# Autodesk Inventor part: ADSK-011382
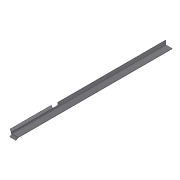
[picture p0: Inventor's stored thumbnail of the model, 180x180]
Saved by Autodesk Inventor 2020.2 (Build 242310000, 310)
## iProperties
Created: 1999-12
Part Number: ADSK-011382
Material: 1.0312 DC05
Document SubType Name: Tôlerie
Designer: sspink
Density: 1 g/cm^3
Sheet Metal Rule: Stahlblech 1.0312 - DC05 -   3.0 mm
Appearance: Metal-Steel(Polish)
Mass: 468.169 g
Surface Area: 3221.87 cm^2
Volume: 468.169 cm^3
Sheet Metal Width: 102,286 mm
Sheet Metal Length: 1548,047 mm
Sheet Metal Area: 158343,243 mm^2
Flat Pattern Width: 10.2286 cm
Flat Pattern Length: 154.805 cm
Flat Pattern Area: 1583.43 cm^2
Control State: 0
Master: False
Checked Out: False
Shininess: 57.0
Length Units: 11269
Angle Units: 11279
Time Units: 11290
Mass Units: 11283
Length Display Precision: 3
Angle Display Precision: 2
Compacted: True
CUTLENGTH: 3.81 X 61.03 (233 SI)
MATERIAL DESC: SHEET,S/S, 11 GA
MATERIAL_NUMBER: A084638
G_L: 102,3x1548 mm
Thickness: 3,000 mm
Dimensions: 53,1x1545,7x78,6 mm
Mass: 0,468 kg
Semi finished: Stahlblech 1.0312 - DC05 -   3.0 mm
VLT_Material: 1.0312 DC05
Density: 8.03
Volumn: 482.19162532113285
Area: 3142.4654297786715
PropertySet Name: Model Information
Author: sspink
Revision Number: -
Title: ADSK-011382
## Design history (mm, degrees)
node "Solide1"
  node "Konturlasche1"
  node "Lasche1"
  node "Lasche2"
sketch "Sketch1"
  geometry: L1 (0, 0)-(0, 38); L2 (0, 0)-(63.5, 0); 1 further point
  constraints: 4 end point, 1 coincident, 1 horizontal, 1 perpendicular
  dimensions: "d56" = 63.5 distance of L1.start L2.end; "d57" = 38 distance of L1.start L1.end
sketch "Skizze13"
  geometry: L1 (0, 460)-(0, 54); L2 (0, 54)-(25, 54); L3 (25, 54)-(25, 460); L4 (25, 460)-(0, 460)
  constraints: 8 end point
feature "Grobblech3" dims "d55" = 3 (= Thickness), "d82" = 3 (= BendReliefWidth), "d83" = 1.5 (= BendReliefDepth), "d84" = 6 (= MinimumRemnant), "d85" = 3 (= TransitionRadius), "d86" = 406, "d87" = 0, "d88" = 25, "d89" = 30 deg, "d90" = 3 (= BendRadius), "d91" = 12 (= CornerReliefSize), "d92" = 3 (= TailleJeu), "d93" = 3 (= TailleRayonJacobi), "SeamGap" = 0.00508
feature "Biegung6" dims "d55" = 3 (= Thickness), "d82" = 3 (= BendReliefWidth), "d83" = 1.5 (= BendReliefDepth), "d84" = 6 (= MinimumRemnant), "d85" = 3 (= TransitionRadius), "d88" = 25, "d89" = 30 deg, "d90" = 3 (= BendRadius), "SeamGap" = 0.00508
feature "Ecke3" dims "d88" = 25, "d89" = 30 deg, "d91" = 12 (= CornerReliefSize), "d92" = 3 (= TailleJeu), "d93" = 3 (= TailleRayonJacobi)
feature "Grobblech1" dims "d55" = 3 (= Thickness), "d58" = 3 (= BendReliefWidth), "d59" = 1.5 (= BendReliefDepth), "d60" = 6 (= MinimumRemnant), "d61" = 3 (= TransitionRadius), "d62" = 1524, "d63" = 3 (= BendRadius), "d64" = 3, "d65" = 12 (= CornerReliefSize), "d66" = 3 (= TailleJeu), "d67" = 3 (= TailleRayonJacobi), "SeamGap" = 0.00508
feature "Biegung4" dims "d55" = 3 (= Thickness), "d58" = 3 (= BendReliefWidth), "d59" = 1.5 (= BendReliefDepth), "d60" = 6 (= MinimumRemnant), "d61" = 3 (= TransitionRadius), "d63" = 3 (= BendRadius), "d64" = 3, "SeamGap" = 0.00508
feature "Ecke1" dims "d64" = 3, "d65" = 12 (= CornerReliefSize), "d66" = 3 (= TailleJeu), "d67" = 3 (= TailleRayonJacobi)
sketch "Skizze11"
  geometry: L1 through (-30.25, 0) direction (1, -1.04e-17); L2 through (0, 12.5) direction (-8.53e-18, 1); L3 (0, 25)-(-60.5, 25); L4 (-60.5, 25)-(-60.5, 0)
  constraints: 6 end point, 1 horizontal, 1 perpendicular, 1 vertical
feature "Grobblech2" dims "d55" = 3 (= Thickness), "d68" = 3 (= BendReliefWidth), "d69" = 1.5 (= BendReliefDepth), "d70" = 6 (= MinimumRemnant), "d71" = 3 (= TransitionRadius), "d72" = 25, "d73" = 30 deg, "d74" = 3 (= BendRadius), "d75" = 12 (= CornerReliefSize), "d76" = 3 (= TailleJeu), "d77" = 3 (= TailleRayonJacobi), "SeamGap" = 0.00508
feature "Biegung5" dims "d55" = 3 (= Thickness), "d68" = 3 (= BendReliefWidth), "d69" = 1.5 (= BendReliefDepth), "d70" = 6 (= MinimumRemnant), "d71" = 3 (= TransitionRadius), "d72" = 25, "d73" = 30 deg, "d74" = 3 (= BendRadius), "SeamGap" = 0.00508
feature "Ecke2" dims "d72" = 25, "d73" = 30 deg, "d75" = 12 (= CornerReliefSize), "d76" = 3 (= TailleJeu), "d77" = 3 (= TailleRayonJacobi)
sketch "Skizze12"
  geometry: L1 (0, 0)-(1524, 0) reference; L2 (1524, 0)-(1524, -35) reference; L3 (1064, 0)-(1064, -25); L4 (1064, -25)-(1524, -25); 1 further point
  constraints: 4 end point, 2 point on line, 1 horizontal, 1 vertical
  dimensions: "d78" = 460 distance of L3.end L4.end; "d79" = 25 distance of L3.start L3.end
feature "Ausklinkung1" dims "d80" = 3 (= Thickness), "d81" = 0
node "Corps solides"
node "Corps surfaciques"
feature "Definition1"
other parameters: "Thickness" = 3 (derived), "BendRadius" = 3 (= Thickness), "BendReliefWidth" = 3 (= Thickness), "BendReliefDepth" = 1.5 (= 0.5 x Thickness), "CornerReliefSize" = 12 (= 4 x Thickness), "MinimumRemnant" = 6 (= 2 x Thickness), "TransitionRadius" = 3 (= BendRadius), "TailleRayonJacobi" = 3 (= BendRadius), "TailleJeu" = 3 (= Thickness), "Thickness_Kopieren" = 3.175 [user parameter], "Thickness_Kopieren" = 3.175, "BendRadius" = 3, "BendReliefDepth" = 1.5, "BendReliefWidth" = 3, "CornerReliefSize" = 12, "MinimumRemnant" = 6, "TailleJeu" = 3, "TailleRayonJacobi" = 3, "Thickness" = 3, "TransitionRadius" = 3
